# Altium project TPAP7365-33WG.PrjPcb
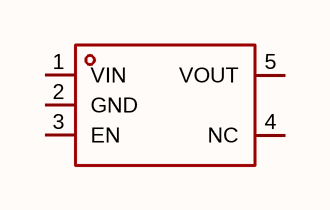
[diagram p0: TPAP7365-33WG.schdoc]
1 sheet, 1 parts. Net scope: global (net labels, ports and power ports of the same name join across sheets).

## Sheet TPAP7365-33WG.schdoc
size 127 x 101 mm

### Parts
U?  tpap7365-33wg  [SOT-23-5_L3.0-W1.7-P0.95-LS2.8-BR]  (value not drawn)

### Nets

Not connected (* = marked no-connect by the designer): U? 1(VIN) 2(GND) 3(EN) 4(NC) 5(VOUT)

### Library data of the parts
U? = tpap7365-33wg: 输出极性:正极;工作电压:5.5V;输出电压:3.3V;输出电流:600mA;电源纹波抑制比(PSRR):80dB@(100Hz);输出类型:固定;; Manufacturer: TECH PUBLIC(台舟); AddInBom: yes; ModelId: 0a2a1b8f50944f73965918ad6e5fe167; ModelName: SOT-23-5_L2.9-W1.6-H1.1-LS2.8-P0.95; ModelTransform: 114.173,109.636,0,180,0,0,0,0,0; Output Configuration: 正极; Voltage - Supply: 5.5V; Output Voltage: 3.3V; Output Current: 600mA; Voltage Dropout: 320mV@(600mA); standby current: 2uA; Output Type: 固定; Number of Outputs: 1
